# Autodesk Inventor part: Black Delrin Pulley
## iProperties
Title: Black Delrin Pulley
Author: Shawn Winkler
Created: 2001-06
Part Number: CBL-820
Material: Delrin, Black
Description: Delrin Cable Pulley
Document SubType Name: Modeling
Designer: Shawn Winkler
Engineer: Shawn Winkler
Control State: 0
Master: False
Checked Out: False
Last Check In By: mln049
Last Check In Date: 2001-06-14
PropertySet Name: Design Tracking Control
Shininess: 69.0
PropertySet Name: _Private Model Information
Density: 1.425
Volumn: 0.13260531061328662
Area: 2.551127740632281
PropertySet Name: Model Information
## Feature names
1. Revolution1
